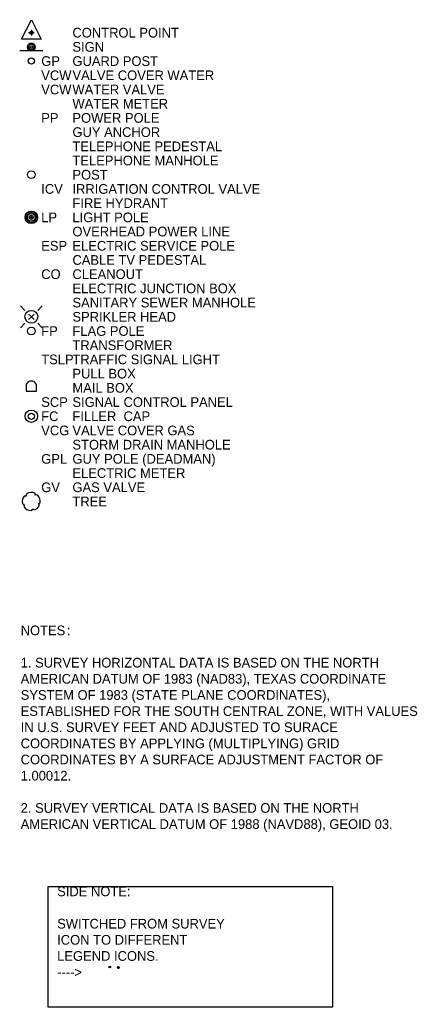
# Model space of a CAD drawing. Extents: x 2250985 to 2256614, y 13788357 to 13792478.
# Drawn here: x 2250985 to 2251601, y 13790192 to 13791721 of the extents above; entities that cross this region are included whole.
import ezdxf

# ---------------------------------------------------------------- set-up
doc = ezdxf.new("R2010")
doc.units = 0
for name, color, linetype in [('Default', 7, 'Continuous'), ('E_Control_Control Point See GPS AZM_CP', 7, 'Continuous'), ('E_Datum Note_Anno', 7, 'Continuous'), ('E_Road_Guard_Guard Post_GP', 7, 'Continuous'), ('E_Road_Pavement_Edge of Pavement_EP', 7, 'Continuous'), ('E_Structure_Filler Cap_FC', 7, 'Continuous'), ('E_Structure_Flag Pole_FP', 7, 'Continuous'), ('E_Structure_Light_Light Pole Small_LP', 7, 'Continuous'), ('E_Structure_Mail Box_MB', 7, 'Continuous'), ('E_Structure_Post Generic_PST', 7, 'Continuous'), ('E_Structure_Sign_Sign And Post Single_SGN', 7, 'Continuous'), ('E_Structure_Sprinkler Head_SPK', 7, 'Continuous'), ('E_Vegetation_Tree_Tree Larger Than TRE_TREE', 7, 'Continuous'), ('LEGEND', 7, 'Continuous'), ('VIEW', 7, 'Continuous')]:
    doc.layers.add(name, color=color, linetype=linetype)

# ---------------------------------------------------------------- blocks, each defined once
blk = doc.blocks.new('traverse_1')
at = {"layer": 'Default'}
for p, q in [((-0.0502, -0.033), (0.0004, 0.0659)), ((0.0004, 0.0659), (0.0498, -0.033)), ((0.0498, -0.033), (-0.0502, -0.033))]:
    blk.add_line(p, q, dxfattribs=at)
blk.add_circle((0, 0), 0.0073, dxfattribs=at)
at = {"layer": 'VIEW'}
for p, q in [((0.0141, 0), (-0.0141, 0)), ((0, 0.0141), (0, -0.0141))]:
    blk.add_line(p, q, dxfattribs=at)
blk = doc.blocks.new('LP')
at = {"layer": 'E_Structure_Light_Light Pole Small_LP'}
for radius in [0.128, 0.104, 0.08, 0.0431, 0.0154]:
    blk.add_circle((0, 0), radius, dxfattribs=at)

msp = doc.modelspace()

# ---------------------------------------------------------------- linework, layer by layer
at = {"layer": 'E_Road_Guard_Guard Post_GP'}
msp.add_circle((2251003, 13791657.1), 4.87, dxfattribs=at)
at = {"layer": 'E_Road_Pavement_Edge of Pavement_EP'}
msp.add_lwpolyline([(2251029.1, 13790378.8), (2251469.6, 13790378.8), (2251469.6, 13790191.9), (2251029.1, 13790191.9)], close=True, dxfattribs=at)
at = {"layer": 'E_Structure_Filler Cap_FC'}
for radius in [9.56, 4.78]:
    msp.add_circle((2251003, 13791107.1), radius, dxfattribs=at)
at = {"layer": 'E_Structure_Flag Pole_FP'}
msp.add_circle((2251003, 13791239.1), 6, dxfattribs=at)
at = {"layer": 'E_Structure_Light_Light Pole Small_LP'}
for p, q in [((2251136.5, 13790254), (2251135.9, 13790254.3)), ((2251136.7, 13790252.7), (2251136, 13790252.2)), ((2251137.6, 13790254.7), (2251137.5, 13790255.5)), ((2251137.8, 13790252.1), (2251137.9, 13790251.4)), ((2251138.8, 13790254.2), (2251139.4, 13790254.6)), ((2251138.9, 13790252.9), (2251139.6, 13790252.6))]:
    msp.add_line(p, q, dxfattribs=at)
for centre, radius in [((2251003, 13791415.1), 9.6), ((2251003, 13791415.1), 7.8), ((2251003, 13791415.1), 6), ((2251003, 13791415.1), 3.23), ((2251003, 13791415.1), 1.15), ((2251137.7, 13790253.4), 1.28)]:
    msp.add_circle(centre, radius, dxfattribs=at)
at = {"layer": 'E_Structure_Mail Box_MB'}
for p, q in [((2250995.1, 13791156.4), (2250995.1, 13791145.9)), ((2251003, 13791151.1), (2251003, 13791151.1)), ((2251010.9, 13791145.9), (2251010.9, 13791156.4)), ((2250995.1, 13791145.9), (2251010.9, 13791145.9))]:
    msp.add_line(p, q, dxfattribs=at)
msp.add_arc((2251003, 13791153.1), 8.53, 22.5706, 157.4294, dxfattribs=at)
at = {"layer": 'E_Structure_Post Generic_PST'}
msp.add_circle((2251003, 13791481.1), 6, dxfattribs=at)
at = {"layer": 'E_Structure_Sign_Sign And Post Single_SGN'}
msp.add_line((2251021, 13791673.1), (2250985, 13791673.1), dxfattribs=at)
for radius in [6, 4.1, 1.83]:
    msp.add_circle((2251003, 13791679.1), radius, dxfattribs=at)
at = {"layer": 'E_Structure_Sprinkler Head_SPK'}
for p, q in [((2250986.1, 13791278.1), (2250993.1, 13791271)), ((2251020, 13791278.1), (2251012.9, 13791271)), ((2250998.8, 13791265.4), (2251003, 13791261.1)), ((2251003, 13791261.1), (2250998.8, 13791256.9)), ((2251007.3, 13791265.4), (2251003, 13791261.1)), ((2251003, 13791261.1), (2251007.3, 13791256.9)), ((2250993.1, 13791251.2), (2250986.1, 13791244.2)), ((2251012.9, 13791251.2), (2251020, 13791244.2))]:
    msp.add_line(p, q, dxfattribs=at)
msp.add_circle((2251003, 13791261.1), 10, dxfattribs=at)
at = {"layer": 'E_Vegetation_Tree_Tree Larger Than TRE_TREE'}
msp.add_line((2251003, 13790975.1), (2251003, 13790975.1), dxfattribs=at)
for centre, radius, start, end in [((2250999.9, 13790975.8), 11.1, 136.239, 199.4725), ((2250992.8, 13790977.4), 6.1, 71.3366, 98.5995), ((2250998.3, 13790984.3), 3.68, 135.858, 197.7856), ((2251003, 13790975.1), 13.9, 65.8644, 122.1722), ((2251003, 13790985.6), 6.1, 354.0845, 21.3475), ((2251010.9, 13790981.8), 3.68, 58.606, 120.5335), ((2251003, 13790975.1), 13.9, 351.6313, 44.9243), ((2250992.8, 13790973.7), 3.68, 206.4553, 268.3828), ((2250997.5, 13790966.3), 6.1, 141.9339, 169.1968), ((2251003, 13790975.1), 13.9, 213.692, 268.2244), ((2251003, 13790975.1), 13.9, 289.109, 330.663), ((2251013.1, 13790977.9), 6.1, 279.8472, 307.1101), ((2251011.6, 13790969.3), 3.68, 344.3687, 46.2962), ((2251001.8, 13790964.8), 3.68, 281.8974, 343.8249), ((2251010.2, 13790967.5), 6.1, 217.376, 244.6389)]:
    msp.add_arc(centre, radius, start, end, dxfattribs=at)

# ---------------------------------------------------------------- block references
at = {"layer": 'E_Control_Control Point See GPS AZM_CP', "xscale": 303.37213868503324, "yscale": 303.37213868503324}
msp.add_blockref('traverse_1', (2251003, 13791701.1), dxfattribs=at)
at = {"layer": 'E_Structure_Light_Light Pole Small_LP', "xscale": 10, "yscale": 10}
msp.add_blockref('LP', (2251124.5, 13790254.2), dxfattribs=at)

# ---------------------------------------------------------------- texts
at = {"layer": 'E_Datum Note_Anno'}
for s, p in [('NOTES', (2250986.5, 13790768)), (':', (2251058.2, 13790768)), ('1. SURVEY HORIZONTAL DATA IS BASED ON THE NORTH ', (2250986.5, 13790718)), ('AMERICAN DATUM OF 1983 (NAD83), TEXAS COORDINATE ', (2250986.5, 13790693)), ('SYSTEM OF 1983 (STATE PLANE COORDINATES), ', (2250986.5, 13790668)), ('ESTABLISHED FOR THE SOUTH CENTRAL ZONE, WITH VALUES ', (2250986.5, 13790643)), ('IN U.S. SURVEY FEET AND ADJUSTED TO SURACE ', (2250986.5, 13790618)), ('COORDINATES BY APPLYING (MULTIPLYING) GRID ', (2250986.5, 13790593)), ('COORDINATES BY A SURFACE ADJUSTMENT FACTOR OF ', (2250986.5, 13790568)), ('1.00012.', (2250986.5, 13790543)), ('2. SURVEY VERTICAL DATA IS BASED ON THE NORTH ', (2250986.5, 13790493)), ('AMERICAN VERTICAL DATUM OF 1988 (NAVD88), GEOID 03.', (2250986.5, 13790468))]:
    msp.add_text(s, height=15, dxfattribs=at).set_placement(p)
at = {"layer": 'E_Road_Pavement_Edge of Pavement_EP'}
for s, p in [('SIDE NOTE:', (2251043, 13790363.8)), ('SWITCHED FROM SURVEY ', (2251043, 13790313.8)), ('ICON TO DIFFERENT ', (2251043, 13790288.8)), ('LEGEND ICONS.', (2251043, 13790263.8)), ('---->', (2251043, 13790238.8))]:
    msp.add_text(s, height=15, dxfattribs=at).set_placement(p)
at = {"layer": 'LEGEND'}
for s, p in [('  CONTROL POINT', (2251055.5, 13791693.6)), ('  SIGN', (2251055.5, 13791671.6)), ('GP', (2251018.3, 13791649.6)), ('  GUARD POST', (2251055.5, 13791649.6)), ('VCW', (2251018.3, 13791627.6)), ('  VALVE COVER WATER', (2251055.5, 13791627.6)), ('VCW', (2251018.3, 13791605.6)), ('  WATER VALVE', (2251055.5, 13791605.6)), ('  WATER METER', (2251055.5, 13791583.6)), ('PP', (2251018.3, 13791561.6)), ('  POWER POLE', (2251055.5, 13791561.6)), ('  GUY ANCHOR', (2251055.5, 13791539.6)), ('  TELEPHONE PEDESTAL', (2251055.5, 13791517.6)), ('  TELEPHONE MANHOLE', (2251055.5, 13791495.6)), ('  POST', (2251055.5, 13791473.6)), ('ICV', (2251018.3, 13791451.6)), ('  IRRIGATION CONTROL VALVE', (2251055.5, 13791451.6)), ('  FIRE HYDRANT', (2251055.5, 13791429.6)), ('LP', (2251018.3, 13791407.6)), ('  LIGHT POLE', (2251055.5, 13791407.6)), ('  OVERHEAD POWER LINE', (2251055.5, 13791385.6)), ('ESP', (2251018.3, 13791363.6)), ('  ELECTRIC SERVICE POLE', (2251055.5, 13791363.6)), ('  CABLE TV PEDESTAL', (2251055.5, 13791341.6)), ('CO', (2251018.3, 13791319.6)), ('  CLEANOUT', (2251055.5, 13791319.6)), ('  ELECTRIC JUNCTION BOX', (2251055.5, 13791297.6)), ('  SANITARY SEWER MANHOLE', (2251055.5, 13791275.6)), ('  SPRIKLER HEAD', (2251055.5, 13791253.6)), ('FP', (2251018.3, 13791231.6)), ('  FLAG POLE', (2251055.5, 13791231.6)), ('  TRANSFORMER', (2251055.5, 13791209.6)), ('TSLP', (2251018.3, 13791187.6)), ('  TRAFFIC SIGNAL LIGHT', (2251055.5, 13791187.6)), ('  PULL BOX', (2251055.5, 13791165.6)), ('  MAIL BOX', (2251055.5, 13791143.6)), ('SCP', (2251018.3, 13791121.6)), ('  SIGNAL CONTROL PANEL', (2251055.5, 13791121.6)), ('FC', (2251018.3, 13791099.6)), ('  FILLER  CAP', (2251055.5, 13791099.6)), ('VCG', (2251018.3, 13791077.6)), ('  VALVE COVER GAS', (2251055.5, 13791077.6)), ('  STORM DRAIN MANHOLE', (2251055.5, 13791055.6)), ('GPL', (2251018.3, 13791033.6)), ('  GUY POLE (DEADMAN)', (2251055.5, 13791033.6)), ('  ELECTRIC METER', (2251055.5, 13791011.6)), ('GV', (2251018.3, 13790989.6)), ('  GAS VALVE', (2251055.5, 13790989.6)), ('  TREE', (2251055.5, 13790967.6))]:
    msp.add_text(s, height=15, dxfattribs=at).set_placement(p)

doc.saveas('drawing.dxf')
